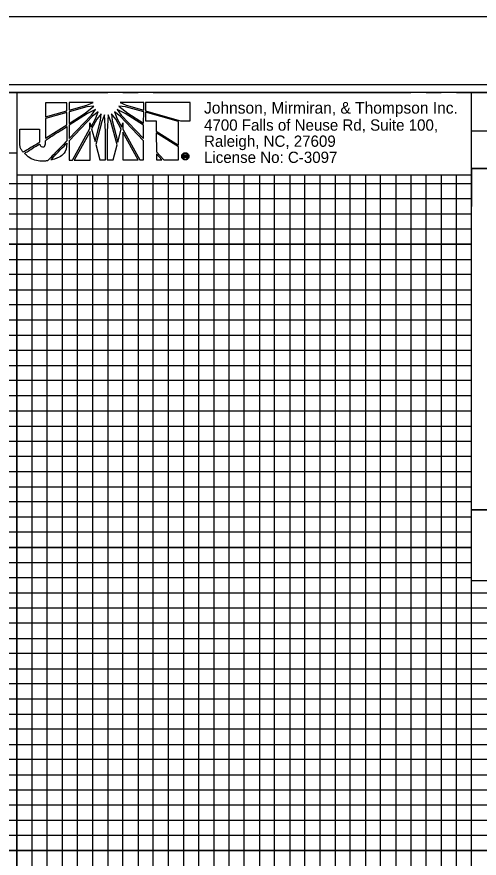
# Model space of a CAD drawing. Extents: x 1647943 to 1651624, y 802691 to 845761.
# Drawn here: x 1650179.3 to 1650331.8, y 803513.5 to 803791 of the extents above; entities that cross this region are included whole.
import ezdxf

# ---------------------------------------------------------------- set-up
doc = ezdxf.new("R2010")
doc.units = 0
for name, color, linetype in [('Prop Dimension Text', 7, 'Continuous'), ('Sheet Cutting Line CELL', 7, 'Continuous'), ('Sheet DOT Grid CELL', 7, 'Continuous'), ('Sheet Plan CELL', 7, 'Continuous'), ('Sheet Plot Border Inside CELL', 7, 'Continuous'), ('Sheet Plot Border Outside CELL', 7, 'Continuous'), ('Sheet Profile CELL', 7, 'Continuous'), ('Sheet Profile Grid Major CELL', 7, 'Continuous'), ('Sheet Profile Grid Middle CELL', 7, 'Continuous'), ('Sheet Profile Grid Minor CELL', 7, 'Continuous'), ('Sheet Sticker Exception Certification CELL', 7, 'Continuous')]:
    doc.layers.add(name, color=color, linetype=linetype)

msp = doc.modelspace()

# ---------------------------------------------------------------- linework, layer by layer
at = {"layer": 'Prop Dimension Text'}
for p, q in [((1650195.79, 803762.71), (1650188.77, 803762.7)), ((1650188.77, 803762.7), (1650188.77, 803758.05)), ((1650195.79, 803760), (1650195.79, 803762.71)), ((1650204.41, 803762.75), (1650196.52, 803762.75)), ((1650196.52, 803762.75), (1650196.52, 803760.23)), ((1650202.4, 803761.86), (1650204.41, 803762.75)), ((1650221.14, 803762.73), (1650213.35, 803762.76)), ((1650213.35, 803762.76), (1650215.32, 803761.84)), ((1650221.14, 803760.21), (1650221.14, 803762.73)), ((1650236.43, 803762.78), (1650221.68, 803762.77)), ((1650221.68, 803762.77), (1650221.68, 803760.06)), ((1650236.44, 803756.74), (1650236.43, 803762.78)), ((1650188.77, 803758.05), (1650195.79, 803760)), ((1650195.79, 803759.49), (1650188.77, 803757.52)), ((1650195.79, 803755.43), (1650195.79, 803759.49)), ((1650196.52, 803760.23), (1650202.4, 803761.86)), ((1650202.4, 803761.31), (1650196.52, 803759.69)), ((1650196.52, 803759.69), (1650196.52, 803755.89)), ((1650201.79, 803759.23), (1650204.69, 803761.59)), ((1650204.69, 803761.59), (1650202.4, 803761.31)), ((1650205.27, 803760.51), (1650202.6, 803759.15)), ((1650203.92, 803758.61), (1650205.27, 803760.51)), ((1650206.08, 803759.66), (1650204.22, 803758.22)), ((1650205.23, 803757.42), (1650206.08, 803759.66)), ((1650211.53, 803759.67), (1650212.39, 803757.42)), ((1650213.39, 803758.23), (1650211.53, 803759.67)), ((1650212.35, 803760.51), (1650213.71, 803758.58)), ((1650215.06, 803759.16), (1650212.35, 803760.51)), ((1650212.96, 803761.6), (1650215.9, 803759.2)), ((1650215.13, 803761.33), (1650212.96, 803761.6)), ((1650221.14, 803759.68), (1650215.13, 803761.33)), ((1650215.32, 803761.84), (1650221.14, 803760.21)), ((1650221.1, 803755.96), (1650221.14, 803759.68)), ((1650221.68, 803760.06), (1650221.68, 803759.98)), ((1650221.68, 803759.98), (1650233.3, 803756.74)), ((1650221.68, 803759.56), (1650221.68, 803759.52)), ((1650232.56, 803756.47), (1650221.68, 803759.56)), ((1650221.68, 803759.52), (1650221.69, 803756.69)), ((1650188.77, 803757.52), (1650188.78, 803750.97)), ((1650196.52, 803755.89), (1650201.79, 803759.23)), ((1650202.6, 803759.15), (1650196.52, 803755.28)), ((1650196.53, 803750.9), (1650203.92, 803758.61)), ((1650204.22, 803758.22), (1650196.53, 803750.16)), ((1650203.76, 803754.74), (1650205.23, 803757.42)), ((1650205.7, 803757.25), (1650203.96, 803754.08)), ((1650205.09, 803749.87), (1650206.9, 803756.87)), ((1650207.09, 803759.04), (1650205.7, 803757.25)), ((1650206.9, 803756.87), (1650207.09, 803759.04)), ((1650208.25, 803758.73), (1650207.29, 803756.48)), ((1650208.56, 803753.19), (1650208.25, 803758.73)), ((1650209.41, 803758.73), (1650209.05, 803753.19)), ((1650210.34, 803756.48), (1650209.41, 803758.73)), ((1650210.53, 803759.04), (1650210.77, 803756.8)), ((1650211.89, 803757.26), (1650210.53, 803759.04)), ((1650210.77, 803756.8), (1650212.59, 803749.71)), ((1650213.71, 803753.97), (1650211.89, 803757.26)), ((1650212.39, 803757.42), (1650213.89, 803754.63)), ((1650221.1, 803750.11), (1650213.39, 803758.23)), ((1650213.71, 803758.58), (1650221.1, 803750.84)), ((1650221.1, 803755.33), (1650215.06, 803759.16)), ((1650215.9, 803759.2), (1650221.1, 803755.96)), ((1650221.69, 803756.69), (1650225.29, 803756.69)), ((1650225.29, 803756.69), (1650225.29, 803753.32)), ((1650233.3, 803756.74), (1650236.44, 803756.74)), ((1650188.78, 803750.97), (1650195.79, 803755.43)), ((1650196.52, 803755.28), (1650196.53, 803750.9)), ((1650197.69, 803743.79), (1650203.41, 803754.16)), ((1650203.41, 803754.16), (1650203.41, 803756.01)), ((1650203.41, 803756.01), (1650203.76, 803754.74)), ((1650203.96, 803754.08), (1650205.09, 803749.87)), ((1650207.29, 803756.48), (1650205.32, 803748.89)), ((1650212.36, 803748.78), (1650210.34, 803756.48)), ((1650212.59, 803749.71), (1650213.71, 803753.97)), ((1650213.89, 803754.63), (1650214.25, 803756.02)), ((1650214.25, 803756.02), (1650214.25, 803753.97)), ((1650214.25, 803753.97), (1650219.87, 803743.81)), ((1650221.1, 803750.84), (1650221.1, 803755.33)), ((1650232.57, 803748.72), (1650232.56, 803756.47)), ((1650203.42, 803753.15), (1650198.24, 803743.79)), ((1650203.47, 803743.8), (1650203.42, 803753.15)), ((1650208.57, 803743.84), (1650208.56, 803753.19)), ((1650209.05, 803753.19), (1650209.06, 803743.84)), ((1650219.29, 803743.85), (1650214.25, 803752.97)), ((1650214.25, 803752.97), (1650214.26, 803743.84)), ((1650225.29, 803753.32), (1650232.57, 803748.72)), ((1650225.29, 803752.74), (1650225.3, 803746.47)), ((1650232.57, 803748.18), (1650225.29, 803752.74)), ((1650196.53, 803750.16), (1650196.53, 803743.79)), ((1650205.32, 803748.89), (1650206.64, 803743.83)), ((1650211.01, 803743.84), (1650212.36, 803748.78)), ((1650221.11, 803743.81), (1650221.1, 803750.11)), ((1650225.3, 803746.47), (1650227.81, 803743.82)), ((1650227.12, 803743.82), (1650225.3, 803745.78)), ((1650225.3, 803745.78), (1650225.3, 803743.82)), ((1650232.57, 803743.82), (1650232.57, 803748.18)), ((1650234.42, 803744.49), (1650234.42, 803745.56)), ((1650234.42, 803745.56), (1650234.86, 803745.56)), ((1650234.86, 803746.19), (1650234.86, 803745.97)), ((1650234.86, 803745.97), (1650234.86, 803746.19)), ((1650234.86, 803745.56), (1650234.86, 803745.36)), ((1650234.86, 803745.36), (1650234.86, 803745.56)), ((1650234.86, 803745.56), (1650234.92, 803745.56)), ((1650196.53, 803743.79), (1650197.69, 803743.79)), ((1650198.24, 803743.79), (1650203.47, 803743.8)), ((1650206.64, 803743.83), (1650208.57, 803743.84)), ((1650209.06, 803743.84), (1650211.01, 803743.84)), ((1650214.26, 803743.84), (1650219.29, 803743.85)), ((1650219.87, 803743.81), (1650221.11, 803743.81)), ((1650225.3, 803743.82), (1650227.12, 803743.82)), ((1650227.81, 803743.82), (1650232.57, 803743.82)), ((1650234.66, 803744.49), (1650234.42, 803744.49)), ((1650234.86, 803745.36), (1650234.66, 803745.36)), ((1650234.66, 803745.36), (1650234.66, 803745.1)), ((1650234.66, 803745.1), (1650234.86, 803745.1)), ((1650234.86, 803744.91), (1650234.66, 803744.91)), ((1650234.66, 803744.91), (1650234.66, 803744.49)), ((1650234.89, 803745.36), (1650234.86, 803745.36)), ((1650234.86, 803745.1), (1650234.86, 803744.91)), ((1650234.86, 803744.91), (1650234.86, 803745.1)), ((1650234.86, 803745.1), (1650234.87, 803745.1)), ((1650234.87, 803744.91), (1650234.86, 803744.91)), ((1650234.86, 803744.07), (1650234.86, 803743.83)), ((1650234.86, 803743.83), (1650234.86, 803744.07)), ((1650234.86, 803744.07), (1650234.87, 803744.07)), ((1650234.87, 803743.83), (1650234.86, 803743.83))]:
    msp.add_line(p, q, dxfattribs=at)
msp.add_lwpolyline([(1650179.28, 803738.96), (1650329.23, 803738.96), (1650329.23, 803766.02), (1650179.28, 803766.02)], close=True, dxfattribs=at)
for points in [[(1650188.77, 803758.05), (1650195.79, 803760), (1650195.79, 803762.71), (1650188.77, 803762.7), (1650188.77, 803758.05)], [(1650202.4, 803761.86), (1650204.41, 803762.75), (1650196.52, 803762.75), (1650196.52, 803760.23), (1650202.4, 803761.86)], [(1650215.32, 803761.84), (1650221.14, 803760.21), (1650221.14, 803762.73), (1650213.35, 803762.76), (1650215.32, 803761.84)], [(1650236.43, 803762.78), (1650221.68, 803762.77), (1650221.68, 803760.06), (1650221.68, 803759.98), (1650233.3, 803756.74), (1650236.44, 803756.74), (1650236.43, 803762.78)], [(1650188.78, 803750.97), (1650195.79, 803755.43), (1650195.79, 803759.49), (1650188.77, 803757.52), (1650188.78, 803750.97)], [(1650196.52, 803759.69), (1650196.52, 803755.89), (1650201.79, 803759.23), (1650204.69, 803761.59), (1650202.4, 803761.31), (1650196.52, 803759.69)], [(1650196.52, 803755.28), (1650196.53, 803750.9), (1650203.92, 803758.61), (1650205.27, 803760.51), (1650202.6, 803759.15), (1650196.52, 803755.28)], [(1650206.08, 803759.66), (1650204.22, 803758.22), (1650196.53, 803750.16), (1650196.53, 803743.79), (1650197.69, 803743.79), (1650203.41, 803754.16), (1650203.41, 803756.01), (1650203.76, 803754.74), (1650205.23, 803757.42), (1650206.08, 803759.66)], [(1650211.53, 803759.67), (1650212.39, 803757.42), (1650213.89, 803754.63), (1650214.25, 803756.02), (1650214.25, 803753.97), (1650219.87, 803743.81), (1650221.11, 803743.81), (1650221.1, 803750.11), (1650213.39, 803758.23), (1650211.53, 803759.67)], [(1650212.35, 803760.51), (1650213.71, 803758.58), (1650221.1, 803750.84), (1650221.1, 803755.33), (1650215.06, 803759.16), (1650212.35, 803760.51)], [(1650212.96, 803761.6), (1650215.9, 803759.2), (1650221.1, 803755.96), (1650221.14, 803759.68), (1650215.13, 803761.33), (1650212.96, 803761.6)], [(1650221.68, 803759.56), (1650221.68, 803759.52), (1650221.69, 803756.69), (1650225.29, 803756.69), (1650225.29, 803753.32), (1650232.57, 803748.72), (1650232.56, 803756.47), (1650221.68, 803759.56)], [(1650207.09, 803759.04), (1650205.7, 803757.25), (1650203.96, 803754.08), (1650205.09, 803749.87), (1650206.9, 803756.87), (1650207.09, 803759.04)], [(1650207.29, 803756.48), (1650205.32, 803748.89), (1650206.64, 803743.83), (1650208.57, 803743.84), (1650208.56, 803753.19), (1650208.25, 803758.73), (1650207.29, 803756.48)], [(1650209.41, 803758.73), (1650209.05, 803753.19), (1650209.06, 803743.84), (1650211.01, 803743.84), (1650212.36, 803748.78), (1650210.34, 803756.48), (1650209.41, 803758.73)], [(1650210.53, 803759.04), (1650210.77, 803756.8), (1650212.59, 803749.71), (1650213.71, 803753.97), (1650211.89, 803757.26), (1650210.53, 803759.04)], [(1650198.24, 803743.79), (1650203.47, 803743.8), (1650203.42, 803753.15), (1650198.24, 803743.79)], [(1650214.26, 803743.84), (1650219.29, 803743.85), (1650214.25, 803752.97), (1650214.26, 803743.84)], [(1650225.29, 803752.74), (1650225.3, 803746.47), (1650227.81, 803743.82), (1650232.57, 803743.82), (1650232.57, 803748.18), (1650225.29, 803752.74), (1650225.29, 803752.74)], [(1650225.3, 803743.82), (1650225.3, 803743.82), (1650227.12, 803743.82), (1650225.3, 803745.78), (1650225.3, 803743.82)], [(1650235.33, 803744.74), (1650235.33, 803744.68), (1650235.33, 803744.64), (1650235.33, 803744.61), (1650235.36, 803744.49), (1650235.14, 803744.49)]]:
    msp.add_lwpolyline(points, dxfattribs=at)
for points, degree in [([(1650186.76, 803753.98), (1650186.76, 803753.98), (1650180.27, 803753.98), (1650180.27, 803753.98), (1650180.27, 803753.98), (1650180.27, 803749.91), (1650180.27, 803749.91), (1650180.27, 803749.91), (1650180.27, 803749.48), (1650180.27, 803749.48), (1650180.27, 803748.21), (1650180.69, 803747.2), (1650181.43, 803746.36), (1650181.43, 803746.36), (1650186.77, 803749.6), (1650186.77, 803749.69), (1650186.77, 803749.69), (1650186.76, 803753.98), (1650186.76, 803753.98)], 3), ([(1650187.78, 803748.13), (1650187.36, 803748.13), (1650187, 803748.37), (1650186.85, 803749.14), (1650186.85, 803749.14), (1650181.81, 803746.02), (1650181.81, 803746.02), (1650183.37, 803744.39), (1650185.85, 803743.42), (1650187.94, 803743.42), (1650188.49, 803743.42), (1650188.9, 803743.47), (1650189.48, 803743.59), (1650189.48, 803743.59), (1650195.8, 803750.12), (1650195.8, 803750.12), (1650195.8, 803750.12), (1650195.79, 803754.85), (1650195.79, 803754.85), (1650195.79, 803754.85), (1650188.78, 803750.38), (1650188.78, 803750.38), (1650188.78, 803748.61), (1650188.35, 803748.14), (1650187.78, 803748.13)], 3), ([(1650187.78, 803748.13), (1650187.36, 803748.13), (1650187, 803748.37), (1650186.85, 803749.14), (1650186.85, 803749.14), (1650181.81, 803746.02), (1650181.81, 803746.02), (1650183.37, 803744.39), (1650185.85, 803743.42), (1650187.94, 803743.42), (1650188.49, 803743.42), (1650188.9, 803743.47), (1650189.48, 803743.59), (1650189.48, 803743.59), (1650195.8, 803750.12), (1650195.8, 803750.12), (1650195.8, 803750.12), (1650195.79, 803754.85), (1650195.79, 803754.85), (1650195.79, 803754.85), (1650188.78, 803750.38), (1650188.78, 803750.38), (1650188.78, 803748.61), (1650188.35, 803748.14), (1650187.78, 803748.13)], 3), ([(1650195.8, 803749.38), (1650195.8, 803749.38), (1650190.34, 803743.74), (1650190.34, 803743.74), (1650193.01, 803744.4), (1650195.68, 803746.17), (1650195.8, 803749.38)], 3), ([(1650234.86, 803743.83), (1650234.54, 803743.83), (1650234.25, 803743.95), (1650234.02, 803744.18), (1650233.78, 803744.41), (1650233.67, 803744.69), (1650233.67, 803745.02), (1650233.67, 803745.35), (1650233.78, 803745.64), (1650234.02, 803745.85), (1650234.25, 803746.08), (1650234.52, 803746.19), (1650234.86, 803746.19)], 3), ([(1650234.86, 803745.97), (1650234.59, 803745.97), (1650234.37, 803745.88), (1650234.18, 803745.71), (1650234, 803745.52), (1650233.9, 803745.29), (1650233.9, 803745.02), (1650233.9, 803744.76), (1650234, 803744.53), (1650234.18, 803744.34), (1650234.37, 803744.16), (1650234.59, 803744.07), (1650234.86, 803744.07)], 3), ([(1650234.86, 803746.19), (1650235.19, 803746.19), (1650235.47, 803746.08), (1650235.7, 803745.85), (1650235.94, 803745.64), (1650236.06, 803745.36), (1650236.06, 803745.03)], 3), ([(1650234.87, 803744.07), (1650235.13, 803744.07), (1650235.35, 803744.16), (1650235.54, 803744.34), (1650235.72, 803744.53), (1650235.82, 803744.76), (1650235.82, 803745.03), (1650235.82, 803745.29), (1650235.72, 803745.52), (1650235.54, 803745.71), (1650235.35, 803745.88), (1650235.13, 803745.97), (1650234.86, 803745.97)], 3), ([(1650234.92, 803745.56), (1650235.2, 803745.56), (1650235.33, 803745.45), (1650235.33, 803745.24), (1650235.33, 803745.14), (1650235.3, 803745.06), (1650235.21, 803745)], 3), ([(1650234.87, 803745.1), (1650235.02, 803745.1), (1650235.1, 803745.15), (1650235.1, 803745.24), (1650235.1, 803745.32), (1650235.03, 803745.36), (1650234.89, 803745.36)], 3), ([(1650236.06, 803745.03), (1650236.06, 803744.69), (1650235.94, 803744.41), (1650235.72, 803744.18), (1650235.48, 803743.95), (1650235.2, 803743.83), (1650234.87, 803743.83)], 3), ([(1650235.05, 803744.87), (1650235.02, 803744.89), (1650234.96, 803744.91), (1650234.87, 803744.91)], 2), ([(1650235.14, 803744.49), (1650235.11, 803744.55), (1650235.09, 803744.61), (1650235.09, 803744.68), (1650235.09, 803744.78), (1650235.08, 803744.84), (1650235.05, 803744.87)], 3), ([(1650235.21, 803745), (1650235.28, 803744.97), (1650235.32, 803744.88), (1650235.33, 803744.74)], 2)]:
    msp.add_open_spline(points, degree=degree, dxfattribs=at)
at = {"layer": 'Sheet Cutting Line CELL'}
msp.add_line((1650546.28, 803791.02), (1648862.28, 803791.02), dxfattribs=at)
at = {"layer": 'Sheet DOT Grid CELL'}
for p, q in [((1650229.28, 803266.02), (1650229.28, 803718.48)), ((1650279.28, 803266.02), (1650279.28, 803718.48)), ((1650329.23, 803716.02), (1649029.28, 803716.02)), ((1650179.28, 803266.02), (1650179.28, 803716.02)), ((1650329.23, 803666.02), (1649029.28, 803666.02)), ((1650329.28, 803266.02), (1650329.28, 803628.47)), ((1650329.28, 803616.02), (1649029.28, 803616.02)), ((1650529.28, 803566.02), (1649029.28, 803566.02)), ((1650529.28, 803516.02), (1649029.28, 803516.02))]:
    msp.add_line(p, q, dxfattribs=at)
at = {"layer": 'Sheet Plan CELL'}
msp.add_line((1650329.23, 803740.94), (1650329.23, 803728.45), dxfattribs=at)
msp.add_line((1650329.23, 803740.94), (1650329.23, 803728.45), dxfattribs=at)
msp.add_line((1650329.23, 803740.94), (1650329.23, 803728.45), dxfattribs=at)
at = {"layer": 'Sheet Plot Border Inside CELL'}
msp.add_lwpolyline([(1648875.28, 802713.47), (1650541.78, 802713.47), (1650541.78, 803768.57), (1648875.28, 803768.57)], close=True, dxfattribs=at)
at = {"layer": 'Sheet Plot Border Outside CELL'}
msp.add_lwpolyline([(1648862.28, 802691.02), (1650546.28, 802691.02), (1650546.28, 803791.02), (1648862.28, 803791.02)], close=True, dxfattribs=at)
at = {"layer": 'Sheet Profile CELL'}
msp.add_line((1650329.23, 803753.47), (1650529.28, 803753.47), dxfattribs=at)
for points in [[(1650529.28, 803766.02), (1649029.28, 803766.02), (1649029.28, 802716.02), (1650529.28, 802716.02)], [(1650329.23, 803766.02), (1650529.28, 803766.02), (1650529.28, 803740.97), (1650329.23, 803740.97)], [(1650329.23, 803740.97), (1650429.28, 803740.97), (1650429.28, 803628.47), (1650329.23, 803628.47)]]:
    msp.add_lwpolyline(points, close=True, dxfattribs=at)
at = {"layer": 'Sheet Profile Grid Major CELL'}
for points in [[(1649879.28, 803266.02), (1649929.28, 803266.02), (1649929.28, 803766.02), (1649979.28, 803766.02), (1649979.28, 803266.02), (1650029.28, 803266.02), (1650029.28, 803766.02), (1650079.28, 803766.02), (1650079.28, 803266.02), (1650129.28, 803266.02), (1650129.28, 803766.02), (1650179.28, 803766.02), (1650179.28, 803266.02), (1650229.28, 803266.02), (1650229.28, 803738.96)], [(1650229.28, 803766.02), (1650279.28, 803766.02)], [(1650279.23, 803738.96), (1650279.23, 803266.02), (1650329.23, 803266.02), (1650329.23, 803766.02), (1650355.53, 803766.02)], [(1649029.28, 803716.02), (1650329.28, 803716.02)], [(1650329.28, 803666.02), (1649029.28, 803666.02), (1649029.28, 803616.02), (1650329.28, 803616.02)], [(1650529.28, 803566.02), (1649029.28, 803566.02), (1649029.28, 803516.02), (1650529.28, 803516.02)]]:
    msp.add_lwpolyline(points, dxfattribs=at)
at = {"layer": 'Sheet Profile Grid Middle CELL'}
for points in [[(1649854.28, 803766.02), (1649904.28, 803766.02), (1649904.28, 803266.02), (1649954.28, 803266.02), (1649954.28, 803766.02), (1650004.28, 803766.02), (1650004.28, 803266.02), (1650054.28, 803266.02), (1650054.28, 803766.02), (1650104.28, 803766.02), (1650104.28, 803266.02), (1650154.28, 803266.02), (1650154.28, 803766.02), (1650204.28, 803766.02)], [(1650254.28, 803766.02), (1650304.28, 803766.02)], [(1650204.28, 803738.96), (1650204.28, 803266.02), (1650254.28, 803266.02), (1650254.28, 803738.96)], [(1650304.28, 803738.96), (1650304.28, 803266.02), (1650354.28, 803266.02), (1650354.28, 803604.97)], [(1650329.28, 803691.02), (1649029.28, 803691.02), (1649029.28, 803641.02), (1650329.28, 803641.02)], [(1650529.28, 803591.02), (1649029.28, 803591.02), (1649029.28, 803541.02), (1650354.28, 803541.02)]]:
    msp.add_lwpolyline(points, dxfattribs=at)
at = {"layer": 'Sheet Profile Grid Minor CELL'}
for p, q in [((1650329.23, 803761.02), (1650329.28, 803761.02)), ((1650329.28, 803756.02), (1650329.23, 803756.02)), ((1650329.23, 803751.02), (1650329.28, 803751.02)), ((1650329.23, 803631.02), (1649079.28, 803631.02)), ((1650329.28, 803626.02), (1649079.28, 803626.02)), ((1650329.28, 803621.02), (1649079.28, 803621.02)), ((1649079.28, 803611.02), (1650329.28, 803611.02)), ((1650329.28, 803606.02), (1649079.28, 803606.02)), ((1649079.28, 803601.02), (1650479.28, 803601.02)), ((1650479.28, 803581.02), (1649079.28, 803581.02)), ((1649079.28, 803576.02), (1650479.28, 803576.02)), ((1650479.28, 803556.02), (1649079.28, 803556.02)), ((1649079.28, 803551.02), (1650479.28, 803551.02)), ((1650479.28, 803531.02), (1649079.28, 803531.02)), ((1649079.28, 803526.02), (1650479.28, 803526.02)), ((1650479.28, 803521.02), (1649079.28, 803521.02))]:
    msp.add_line(p, q, dxfattribs=at)
for points in [[(1650174.28, 803266.02), (1650174.28, 803766.02), (1650184.28, 803766.02)], [(1650189.28, 803766.02), (1650194.28, 803766.02)], [(1650199.28, 803766.02), (1650209.28, 803766.02)], [(1650214.28, 803766.02), (1650219.28, 803766.02)], [(1650224.28, 803766.02), (1650234.28, 803766.02)], [(1650239.28, 803766.02), (1650244.28, 803766.02)], [(1650249.28, 803766.02), (1650259.28, 803766.02)], [(1650264.28, 803766.02), (1650269.28, 803766.02)], [(1650274.28, 803766.02), (1650284.28, 803766.02)], [(1650289.28, 803766.02), (1650294.28, 803766.02)], [(1650299.28, 803766.02), (1650309.28, 803766.02)], [(1650314.28, 803766.02), (1650319.28, 803766.02)], [(1650324.28, 803766.02), (1650334.28, 803766.02)], [(1650179.28, 803746.02), (1649079.28, 803746.02), (1649079.28, 803736.02), (1650329.28, 803736.02)], [(1650329.28, 803746.02), (1650329.23, 803746.02)], [(1650184.28, 803738.96), (1650184.28, 803266.02), (1650189.28, 803266.02), (1650189.28, 803738.96)], [(1650194.28, 803738.96), (1650194.28, 803266.02), (1650199.28, 803266.02), (1650199.28, 803738.96)], [(1650209.28, 803738.96), (1650209.28, 803266.02), (1650214.28, 803266.02), (1650214.28, 803738.96)], [(1650219.28, 803266.02), (1650224.28, 803266.02), (1650224.28, 803738.96)], [(1650219.28, 803738.96), (1650219.28, 803266.02)], [(1650234.28, 803738.96), (1650234.28, 803266.02), (1650239.28, 803266.02), (1650239.28, 803738.96)], [(1650244.28, 803738.96), (1650244.28, 803266.02), (1650249.28, 803266.02), (1650249.28, 803738.96)], [(1650259.28, 803738.96), (1650259.28, 803266.02), (1650264.28, 803266.02), (1650264.28, 803738.96)], [(1650269.28, 803738.96), (1650269.28, 803266.02), (1650274.28, 803266.02), (1650274.28, 803738.96)], [(1650284.28, 803738.96), (1650284.28, 803266.02), (1650289.28, 803266.02), (1650289.28, 803738.96)], [(1650294.28, 803738.96), (1650294.28, 803266.02), (1650299.28, 803266.02), (1650299.28, 803738.96)], [(1650309.28, 803738.96), (1650309.28, 803266.02), (1650314.28, 803266.02), (1650314.28, 803738.96)], [(1650319.28, 803738.96), (1650319.28, 803266.02), (1650324.28, 803266.02), (1650324.28, 803738.96)], [(1650329.23, 803731.02), (1649079.28, 803731.02), (1649079.28, 803726.02), (1650329.28, 803726.02)], [(1650329.28, 803721.02), (1649079.28, 803721.02), (1649079.28, 803711.02), (1650329.28, 803711.02)], [(1650329.28, 803706.02), (1649079.28, 803706.02), (1649079.28, 803701.02), (1650329.28, 803701.02)], [(1650329.28, 803696.02), (1649079.28, 803696.02), (1649079.28, 803686.02), (1650329.28, 803686.02)], [(1650329.28, 803681.02), (1649079.28, 803681.02), (1649079.28, 803676.02), (1650329.28, 803676.02)], [(1650329.28, 803671.02), (1649079.28, 803671.02), (1649079.28, 803661.02), (1650329.28, 803661.02)], [(1650329.28, 803655.92), (1649079.38, 803655.92), (1649079.38, 803651.02), (1650329.28, 803651.02)], [(1650329.28, 803646.02), (1649079.28, 803646.02), (1649079.28, 803636.02), (1650329.28, 803636.02)], [(1650479.28, 803596.02), (1649079.28, 803596.02), (1649079.28, 803586.02), (1650479.28, 803586.02)], [(1650479.28, 803571.02), (1649079.28, 803571.02), (1649079.28, 803561.02), (1650479.28, 803561.02)], [(1650479.28, 803546.02), (1649079.28, 803546.02), (1649079.28, 803536.02), (1650479.28, 803536.02)]]:
    msp.add_lwpolyline(points, dxfattribs=at)
at = {"layer": 'Sheet Sticker Exception Certification CELL'}
for p, q in [((1650329.23, 803604.97), (1650329.23, 803628.47)), ((1650329.23, 803628.47), (1650529.27, 803628.47)), ((1650329.23, 803604.97), (1650329.23, 803628.47)), ((1650329.23, 803628.47), (1650529.27, 803628.47)), ((1650529.27, 803604.97), (1650329.23, 803604.97)), ((1650529.27, 803604.97), (1650329.23, 803604.97))]:
    msp.add_line(p, q, dxfattribs=at)

# ---------------------------------------------------------------- texts
at = {"layer": 'Prop Dimension Text'}
for s, height, p in [('Johnson, Mirmiran, & Thompson Inc.', 3.8315, (1650241.03, 803759.09)), ('4700 Falls of Neuse Rd, Suite 100, ', 3.722, (1650241.03, 803753.47)), ('Raleigh, NC, 27609', 3.722, (1650241.03, 803748.15)), ('License No: C-3097', 3.722, (1650241.03, 803742.83))]:
    msp.add_text(s, height=height, rotation=360, dxfattribs=at).set_placement(p)

doc.saveas('drawing.dxf')
